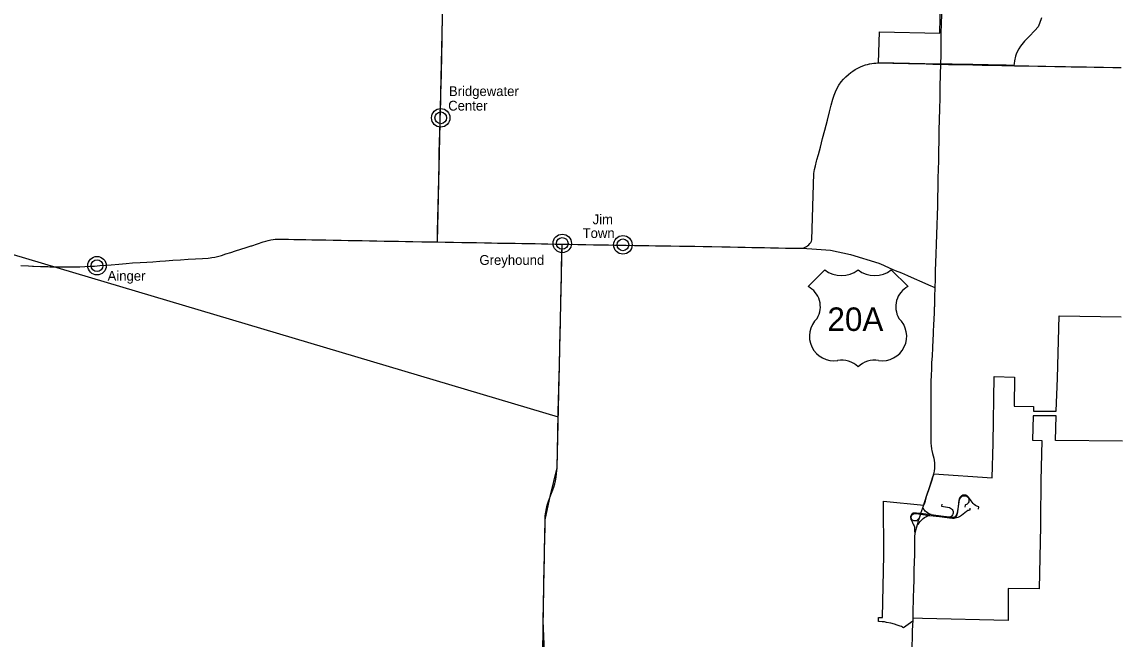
# Model space of a CAD drawing. Extents: x -66 to 795, y 0 to 440.
# Drawn here: x 250.6 to 383.6, y 256.3 to 331.1 of the extents above; entities that cross this region are included whole.
import ezdxf

# ---------------------------------------------------------------- set-up
doc = ezdxf.new("R2010")
doc.units = 0
for name, color, linetype in [('DV_X_Corp_Line', 7, 'Continuous'), ('GM_X_Interchange_Ramps', 7, 'Continuous'), ('GM_X_State_Route', 7, 'Continuous'), ('GM_X_US_Route', 7, 'Continuous'), ('PV_P_Text', 7, 'Continuous'), ('RD_P_Fence', 7, 'Continuous'), ('SH_Data', 7, 'Continuous')]:
    doc.layers.add(name, color=color, linetype=linetype)

msp = doc.modelspace()

# ---------------------------------------------------------------- linework, layer by layer
at = {"layer": 'DV_X_Corp_Line'}
for points in [[(374.21, 331.65), (373.95, 330.96), (373.8, 330.56), (373.41, 330.12), (372.71, 329.39), (372.12, 328.82), (371.64, 328.21), (371.46, 327.88), (371.16, 327.35), (371.03, 326.99), (370.92, 326.44), (370.88, 326.11), (370.83, 325.88), (369.91, 325.9), (368.95, 325.91), (367.73, 325.93), (366.68, 325.95), (365.86, 325.97), (364.94, 325.98), (363.37, 326.01), (362.68, 326.02), (361.95, 326.03), (354.43, 326.2), (354.58, 329.93), (361.89, 329.79), (361.97, 333.52)], [(384.04, 280.33), (375.91, 280.38), (375.98, 283.37), (373.2, 283.39), (373.09, 280.42), (374.23, 280.39), (374.14, 275.5), (374.07, 270.73), (374.07, 270.5), (374.06, 270.02), (373.92, 262.41), (370.14, 262.47), (370.14, 258.59), (359.78, 258.82), (358.61, 258.86), (358.59, 258.51), (357.46, 257.67), (357.41, 257.73), (357.35, 257.78), (357.23, 257.84), (357.05, 257.9), (356.72, 258), (356.36, 258.12), (355.93, 258.24), (355.41, 258.34), (355.16, 258.39), (354.99, 258.42), (354.88, 258.42), (354.54, 258.45), (354.43, 258.46), (354.44, 258.94), (354.91, 258.93), (355.08, 266.49), (355.03, 273.04), (359.92, 272.54), (360.05, 272.85), (360.12, 273.07), (360.31, 273.74), (360.57, 274.55), (360.93, 275.62), (361.14, 276.34), (368.21, 275.87), (368.34, 280.09), (368.48, 288.14), (370.91, 288.09), (370.89, 284.55), (373.22, 284.52), (373.22, 283.94), (375.99, 283.95), (376.13, 287.96), (376.33, 295.52), (383.84, 295.4)]]:
    msp.add_lwpolyline(points, dxfattribs=at)
for centre, radius in [((301.37, 319.52), 1.12), ((301.37, 319.52), 0.71), ((316.1, 304.29), 1.12), ((316.1, 304.29), 0.71), ((323.45, 304.12), 1.12), ((323.45, 304.12), 0.71), ((259.7, 301.59), 1.12), ((259.7, 301.59), 0.71)]:
    msp.add_circle(centre, radius, dxfattribs=at)
at = {"layer": 'GM_X_Interchange_Ramps'}
for points in [[(366.55, 272.07), (366.59, 272.35), (366.37, 272.43), (366.2, 272.52), (366.05, 272.63), (365.92, 272.75), (365.8, 272.9), (365.67, 273.09), (365.48, 273.36), (365.37, 273.53), (365.27, 273.62), (365.15, 273.71), (365.01, 273.76), (364.88, 273.78), (364.76, 273.77), (364.65, 273.75), (364.54, 273.7), (364.45, 273.64), (364.37, 273.58), (364.3, 273.48), (364.25, 273.4), (364.22, 273.31), (364.19, 273.17), (364.08, 272.4), (363.97, 271.61), (363.95, 271.5), (363.91, 271.41), (363.86, 271.31), (363.79, 271.21), (363.72, 271.15), (363.6, 271.09), (363.52, 271.07), (363.42, 271.06), (363.3, 271.06), (363.17, 271.07), (362.99, 271.1), (362.01, 271.21), (360.82, 271.37), (359.55, 271.54), (359.36, 271.56), (359.03, 271.6), (358.87, 271.6), (358.76, 271.6), (358.65, 271.58), (358.54, 271.51), (358.46, 271.44), (358.4, 271.36), (358.34, 271.26), (358.32, 271.15), (358.31, 271.05), (358.34, 270.93), (358.38, 270.82), (358.47, 270.64), (358.62, 270.34), (358.7, 270.18), (358.75, 270.04), (358.79, 269.91), (358.79, 269.74), (358.79, 269.31), (358.87, 269.29)], [(359.32, 270.86), (359.24, 270.89), (359.23, 270.84), (359.14, 270.73), (359.04, 270.67), (358.95, 270.65), (358.83, 270.64), (358.71, 270.65), (358.58, 270.73), (358.5, 270.79), (358.44, 270.9), (358.41, 271.01), (358.41, 271.15), (358.45, 271.27), (358.5, 271.37), (358.56, 271.44), (358.67, 271.51), (358.75, 271.54), (358.86, 271.55), (358.99, 271.53), (359.53, 271.47), (360.66, 271.32), (361.85, 271.17), (363.36, 270.99), (363.46, 271), (363.56, 271.01), (363.68, 271.04), (363.8, 271.12), (363.88, 271.22), (363.93, 271.3), (363.97, 271.39), (364.01, 271.53), (364.05, 271.76), (364.09, 272.1), (364.13, 272.4), (364.21, 272.94), (364.27, 273.2), (364.33, 273.36), (364.39, 273.46), (364.49, 273.55), (364.6, 273.64), (364.74, 273.68), (364.85, 273.69), (364.97, 273.68), (365.1, 273.64), (365.2, 273.57), (365.27, 273.52), (365.34, 273.43), (365.38, 273.32), (365.41, 273.2), (365.41, 273.07), (365.38, 272.95), (365.33, 272.83), (365.27, 272.75), (365.19, 272.69), (365.1, 272.62), (365, 272.58), (364.93, 272.57), (364.89, 272.3)], [(362.11, 272.67), (362.08, 272.45), (362.33, 272.41), (362.8, 272.31), (363.03, 272.26), (363.16, 272.2), (363.29, 272.11), (363.39, 272.01), (363.46, 271.91), (363.49, 271.8), (363.5, 271.69), (363.49, 271.58), (363.47, 271.47), (363.41, 271.38), (363.33, 271.28), (363.25, 271.2), (363.15, 271.15), (363, 271.12), (362.99, 271.1)], [(360.82, 271.37), (360.83, 271.41), (360.65, 271.47), (360.51, 271.54), (360.37, 271.64), (360.23, 271.73), (360.1, 271.84), (360.02, 271.94), (359.95, 272.05), (359.93, 272.12), (359.76, 272.18)], [(363.46, 271), (363.47, 270.97), (363.6, 270.97), (363.75, 271), (363.91, 271.05), (364.09, 271.11), (364.25, 271.18), (364.49, 271.34), (365.1, 271.81), (365.21, 271.89), (365.29, 271.93), (365.38, 271.96), (365.49, 271.99), (365.54, 271.99), (365.57, 272.21)], [(359.15, 270.31), (359.28, 270.27), (359.37, 270.41), (359.5, 270.59), (359.72, 270.82), (359.86, 270.94), (360, 271.05), (360.17, 271.16), (360.31, 271.22), (360.42, 271.27), (360.55, 271.29), (360.66, 271.3), (360.66, 271.32)]]:
    msp.add_lwpolyline(points, dxfattribs=at)
at = {"layer": 'GM_X_State_Route'}
for points in [[(301.31, 319.71), (301.32, 320.19), (301.32, 320.26), (301.37, 321.3), (301.37, 321.35), (301.39, 322.48), (301.42, 323.56), (301.46, 324.77), (301.46, 324.81), (301.48, 325.79), (301.49, 326.18), (301.5, 327.09), (301.51, 327.32), (301.53, 328.68), (301.56, 330), (301.58, 331.46)], [(362.07, 332.48), (362.06, 332.18), (362.03, 330.83), (362.01, 329.88), (361.99, 328.75), (361.99, 327.1), (361.97, 326.03)], [(361.97, 326.03), (361.92, 324.76), (361.88, 323.27), (361.86, 321.93), (361.83, 320.56), (361.8, 319.33), (361.77, 318), (361.75, 316.74), (361.73, 315.46), (361.7, 314.31), (361.67, 313.25), (361.64, 312.19), (361.63, 311.19), (361.63, 310.95), (361.61, 309.94), (361.58, 308.83), (361.54, 307.67), (361.51, 306.56), (361.48, 305.39), (361.44, 304.19), (361.39, 302.99), (361.37, 301.97), (361.32, 300.96), (361.3, 299.93), (361.28, 298.94)], [(300.96, 304.47), (300.99, 305.68), (301.03, 307.36), (301.06, 308.86), (301.1, 310.49), (301.13, 312.08), (301.17, 313.98), (301.19, 315.35), (301.23, 316.57), (301.26, 317.74), (301.26, 317.85), (301.31, 319.17), (301.31, 319.55), (301.31, 319.71), (301.31, 319.71)], [(315.55, 280.57), (315.55, 280.6), (315.55, 280.97), (315.56, 281.58), (315.57, 281.99), (315.6, 283.11), (315.62, 284.2), (315.65, 284.96), (315.7, 286.99), (315.74, 288.11), (315.75, 289.14), (315.77, 290), (315.8, 290.93), (315.81, 292.02), (315.84, 293.27), (315.87, 294.61), (315.94, 297.43), (315.97, 298.78), (316, 300.14), (316.02, 301.41), (316.06, 302.87), (316.1, 304.2)], [(315.5, 277.69), (315.51, 278.56), (315.53, 279.79), (315.55, 280.57)], [(314.67, 273.67), (314.73, 273.81), (314.95, 274.41), (315.07, 274.75), (315.19, 275.14), (315.27, 275.51), (315.36, 275.94), (315.42, 276.4), (315.45, 276.71), (315.48, 277.08), (315.5, 277.58), (315.5, 277.69)], [(314.02, 270.11), (314.02, 270.25), (314.03, 270.64), (314.04, 271.25), (314.05, 271.28), (314.1, 271.72), (314.18, 272.15), (314.27, 272.56), (314.38, 272.92), (314.55, 273.38), (314.67, 273.67)], [(314.22, 248.17), (314.16, 248.78), (314.06, 249.96), (313.97, 250.99), (313.91, 251.77), (313.84, 252.59), (313.79, 253.21), (313.76, 253.69), (313.74, 254.12), (313.73, 254.63), (313.74, 255.53), (313.77, 256.79), (313.79, 258.34), (313.81, 259.46), (313.81, 259.94), (313.81, 260.45), (313.85, 262.15), (313.88, 263.44), (313.91, 264.81), (313.93, 266), (313.95, 267.26), (313.98, 268.62), (314.01, 269.72), (314.02, 270.11)]]:
    msp.add_lwpolyline(points, dxfattribs=at)
at = {"layer": 'GM_X_US_Route'}
for points in [[(346.98, 314.41), (347.16, 315.09), (347.4, 315.97), (347.67, 317.02), (347.94, 318.03), (348.25, 319.24), (348.5, 320.23), (348.72, 321.06), (348.91, 321.8), (349.06, 322.27), (349.22, 322.67), (349.42, 323.1), (349.65, 323.49), (349.93, 323.87), (350.19, 324.2), (350.48, 324.49), (350.79, 324.78), (351.07, 325.01), (351.32, 325.19), (351.6, 325.37), (351.92, 325.54), (352.25, 325.7), (352.53, 325.82), (352.85, 325.93), (353.09, 325.99), (353.34, 326.05), (353.4, 326.06), (353.64, 326.1), (353.88, 326.15), (354.12, 326.16), (354.31, 326.17), (354.31, 326.17)], [(354.31, 326.17), (354.47, 326.18), (355.04, 326.17), (355.22, 326.17), (355.23, 326.17)], [(355.23, 326.17), (355.59, 326.17), (356.18, 326.16), (356.81, 326.15), (357.42, 326.14), (358.09, 326.12), (358.81, 326.11), (359.59, 326.09), (360.21, 326.07), (361.03, 326.04), (361.97, 326.03)], [(361.97, 326.03), (362.91, 326), (364, 325.98), (364.94, 325.97), (365.86, 325.95), (367.01, 325.92), (368.1, 325.91), (369.23, 325.89), (369.39, 325.88)], [(369.39, 325.88), (369.39, 325.88), (370.13, 325.86), (370.72, 325.85)], [(370.72, 325.85), (370.72, 325.85), (370.92, 325.84), (371.73, 325.84), (372.67, 325.82), (373.74, 325.8), (374.74, 325.77), (375.8, 325.76), (376.89, 325.74), (377.1, 325.74), (377.79, 325.72), (378.72, 325.71), (379.67, 325.69), (380.58, 325.68), (381.72, 325.66), (382.84, 325.64), (383.86, 325.62)], [(316.54, 304.2), (316.97, 304.19), (317.99, 304.18), (318.98, 304.15), (319.88, 304.14), (320.68, 304.13), (321.69, 304.11), (322.44, 304.1), (323.13, 304.09), (323.67, 304.08), (323.85, 304.07), (324.86, 304.06), (325.75, 304.05), (326.61, 304.04), (327.42, 304.01), (328.35, 304), (329.28, 303.98), (330.32, 303.96), (331.13, 303.95), (331.16, 303.95), (332.18, 303.94), (333.18, 303.91), (334.25, 303.9), (335.43, 303.88), (336.44, 303.86), (337.38, 303.85), (338.27, 303.83), (339.1, 303.81), (339.9, 303.79), (340.6, 303.78), (341.35, 303.76), (342.3, 303.75), (343.17, 303.73), (343.98, 303.72), (344.65, 303.71), (345.16, 303.72), (345.38, 303.77), (345.56, 303.85), (345.72, 303.93), (345.85, 304.01), (345.98, 304.13), (346.12, 304.28), (346.22, 304.42), (346.31, 304.58), (346.36, 304.74), (346.6, 312.77), (346.68, 313.25), (346.79, 313.68), (346.93, 314.25), (346.97, 314.41), (346.98, 314.41)], [(253.73, 301.48), (253.97, 301.47), (254.52, 301.45), (255.12, 301.44), (255.61, 301.44), (256.28, 301.44), (256.99, 301.44), (257.63, 301.45), (258.23, 301.48), (258.81, 301.53), (259.39, 301.55), (260.03, 301.6), (260.71, 301.66), (261.41, 301.71), (262.34, 301.78), (263.23, 301.85), (264.02, 301.92), (264.92, 301.98), (265.72, 302.03), (266.46, 302.08), (267.3, 302.15), (268.02, 302.2), (268.88, 302.25), (269.82, 302.31), (270.74, 302.37), (271.65, 302.41), (272.48, 302.46), (273.17, 302.5), (273.43, 302.53), (273.63, 302.57), (273.97, 302.64), (274.31, 302.72), (274.78, 302.84), (275.31, 303.02), (275.91, 303.21), (276.49, 303.4), (277.15, 303.61), (277.79, 303.8), (278.38, 303.99), (278.46, 304.02), (279.15, 304.25), (279.84, 304.47), (280.18, 304.57), (280.45, 304.66), (280.76, 304.73), (281.05, 304.78), (281.31, 304.81), (281.63, 304.81), (282.17, 304.8), (282.91, 304.79), (283.56, 304.78), (284.32, 304.76), (285.03, 304.75), (285.74, 304.74), (285.91, 304.74), (286.55, 304.72), (287.46, 304.71), (288.32, 304.69), (289.31, 304.68), (290.14, 304.66), (290.97, 304.65), (291.86, 304.63), (292.74, 304.62), (293.63, 304.59), (294.53, 304.58), (295.39, 304.57), (296.26, 304.55), (297.1, 304.54), (297.99, 304.52), (299.07, 304.5), (300.06, 304.48), (300.96, 304.47), (301.89, 304.45), (302.93, 304.44), (303.91, 304.41), (304.88, 304.39), (305.71, 304.39), (306.69, 304.37), (307.54, 304.35), (308.24, 304.34), (308.57, 304.34), (308.91, 304.34), (309.68, 304.32), (310.4, 304.31), (311.21, 304.3), (311.98, 304.28), (312.8, 304.27), (313.59, 304.25), (314.37, 304.24), (315.25, 304.22), (316.1, 304.2), (316.54, 304.2), (316.54, 304.2)], [(345.16, 303.72), (346.34, 303.63), (348.64, 303.46), (351.04, 302.96), (354.48, 301.9), (355.03, 301.65), (355.81, 301.31), (356.48, 301.02), (357.21, 300.71), (357.94, 300.39), (358.76, 300.04), (359.71, 299.62), (360.51, 299.28), (361.28, 298.94)], [(250.45, 301.62), (251.38, 301.57), (251.86, 301.55), (252.02, 301.54), (252.83, 301.5), (253.38, 301.49), (253.73, 301.48), (253.73, 301.48)], [(361.28, 298.94), (361.28, 298.94), (361.24, 297.81), (361.21, 296.72), (361.21, 296.62), (361.2, 296.57)], [(361.2, 296.57), (361.19, 295.84), (361.12, 294.43), (361.07, 293.62), (361.07, 293.61), (361.05, 293.25)], [(361.05, 293.25), (361.02, 292.65), (360.97, 291.65), (360.93, 290.68), (360.88, 289.81), (360.85, 289), (360.81, 288.34), (360.79, 287.5), (360.78, 286.82), (360.78, 285.81), (360.77, 284.72), (360.77, 283.95), (360.78, 282.94), (360.78, 282.06), (360.78, 281.37), (360.79, 280.85), (360.78, 280.34), (360.79, 280.05), (360.81, 279.8), (360.83, 279.66), (360.87, 279.46), (360.88, 279.35)], [(360.88, 279.35), (360.91, 279.19), (361, 278.83), (361.13, 278.27), (361.19, 277.99), (361.23, 277.68), (361.24, 277.31), (361.22, 277.03), (361.18, 276.69), (361.11, 276.34), (361.09, 276.25)], [(361.09, 276.25), (361, 275.95), (360.79, 275.32), (360.58, 274.67), (360.27, 273.73), (360.02, 272.97)], [(359.97, 272.84), (359.85, 272.44)], [(360.02, 272.97), (359.98, 272.84), (359.97, 272.84)], [(359.85, 272.44), (359.76, 272.18), (359.55, 271.54), (359.53, 271.47), (359.32, 270.86), (359.21, 270.54), (359.15, 270.31), (358.99, 269.77), (358.87, 269.29), (358.84, 269.14), (358.82, 268.73), (358.82, 268.15), (358.81, 267.51), (358.81, 267.21), (358.8, 267), (358.8, 266.91)], [(358.8, 266.91), (358.79, 266.66), (358.79, 266.45), (358.77, 265.78), (358.74, 264.6), (358.71, 263.54), (358.68, 262.35), (358.66, 261.39), (358.66, 261.29)], [(358.66, 261.29), (358.66, 260.99), (358.62, 259.87), (358.6, 258.78)], [(358.59, 258.41), (358.58, 258.15), (358.54, 257.15), (358.52, 256.36), (358.52, 256.35)], [(358.6, 258.78), (358.59, 258.41)], [(358.52, 256.35), (358.49, 255.62), (358.44, 254.39), (358.41, 253.3), (358.39, 252.27), (358.36, 251.08), (358.33, 249.75), (358.31, 248.47), (358.28, 247.24), (358.27, 246.6)]]:
    msp.add_lwpolyline(points, dxfattribs=at)
at = {"layer": 'PV_P_Text'}
for p, q in [((347.94, 301.09), (345.91, 299.06)), ((347.94, 301.09), (345.91, 299.06)), ((358.02, 299.06), (355.99, 301.09)), ((358.02, 299.06), (355.99, 301.09))]:
    msp.add_line(p, q, dxfattribs=at)
for centre, radius, start, end in [((349.95, 303.65), 3.26, 231.813, 308.187), ((349.95, 303.65), 3.26, 231.813, 308.187), ((353.98, 303.65), 3.26, 231.813, 308.187), ((353.98, 303.65), 3.26, 231.813, 308.187), ((344.64, 296.62), 2.75, 329.1175, 62.6108), ((344.64, 296.62), 2.75, 329.1175, 62.6108), ((359.28, 296.62), 2.75, 117.3892, 210.8825), ((359.28, 296.62), 2.75, 117.3892, 210.8825), ((349.04, 293.03), 2.97, 133.0046, 278.7282), ((349.04, 293.03), 2.97, 133.0046, 278.7282), ((354.89, 293.03), 2.97, 261.2718, 46.9954), ((354.89, 293.03), 2.97, 261.2718, 46.9954), ((350.03, 287.49), 2.66, 43.4177, 101.8742), ((350.03, 287.49), 2.66, 43.4177, 101.8742), ((353.95, 287.31), 2.82, 79.9613, 134.7468), ((353.95, 287.31), 2.82, 79.9613, 134.7468)]:
    msp.add_arc(centre, radius, start, end, dxfattribs=at)
at = {"layer": 'RD_P_Fence'}
for points in [[(300.96, 304.47), (301.62, 333.36), (302.27, 364.02)], [(314.22, 248.17), (313.79, 258.55), (313.95, 266.77), (314.03, 270.76), (314.65, 273.62), (315.48, 277.07), (316.09, 304.15)]]:
    msp.add_lwpolyline(points, dxfattribs=at)
at = {"layer": 'SH_Data'}
msp.add_line((159.19, 329.81), (315.62, 283.27), dxfattribs=at)

# ---------------------------------------------------------------- texts
at = {"layer": 'DV_X_Corp_Line'}
for s, height, p in [('Bridgewater', 1.1875, (302.36, 322.16)), ('Center', 1.188, (302.27, 320.4)), ('Jim', 1.188, (319.78, 306.62)), ('Town', 1.188, (318.57, 304.95)), ('Greyhound', 1.188, (306.06, 301.69)), ('Ainger', 1.188, (260.98, 299.77))]:
    msp.add_text(s, height=height, rotation=0, dxfattribs=at).set_placement(p)
at = {"layer": 'PV_P_Text'}
msp.add_text('20A', height=2.85, dxfattribs=at).set_placement((348.25, 293.68))

doc.saveas('drawing.dxf')
